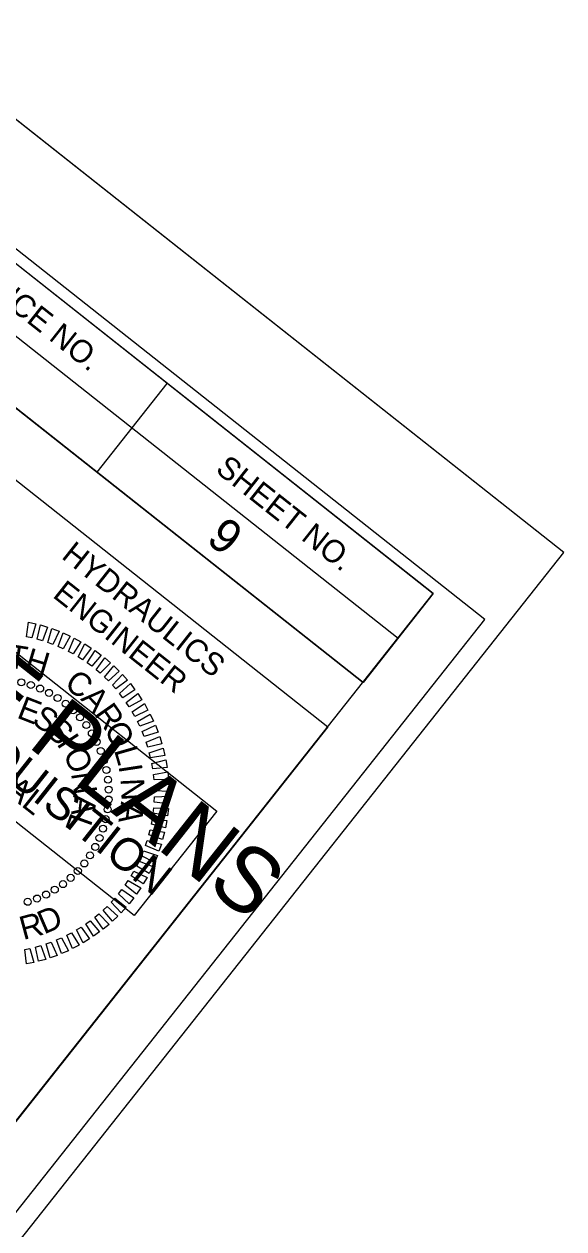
# Model space of a CAD drawing. Extents: x 556999 to 559002, y 505273 to 507273.
# Drawn here: x 558883.2 to 559002.4, y 506079.3 to 506345.6 of the extents above; entities that cross this region are included whole.
import ezdxf

# ---------------------------------------------------------------- set-up
doc = ezdxf.new("R2010")
doc.units = 0
for name, color, linetype in [('Old_Level_21', 7, 'Continuous'), ('Sheet Border Standard 30in CELL', 7, 'Continuous'), ('Sheet Cutting Line CELL', 7, 'Continuous'), ('Sheet Data Field CELL', 7, 'Continuous'), ('Sheet Plot Border Inside CELL', 7, 'Continuous'), ('Sheet Plot Border Outside CELL', 7, 'Continuous'), ('Sheet Sticker Incomplete CELL', 7, 'Continuous')]:
    doc.layers.add(name, color=color, linetype=linetype)

msp = doc.modelspace()

# ---------------------------------------------------------------- linework, layer by layer
at = {"layer": 'Old_Level_21'}
for points in [[(558883.69, 506210.18), (558884.14, 506213.39), (558885.77, 506213), (558884.85, 506209.94)], [(558886.08, 506209.62), (558886.75, 506212.78), (558888.35, 506212.28), (558887.22, 506209.29)], [(558888.43, 506208.88), (558889.32, 506211.99), (558890.88, 506211.38), (558889.54, 506208.48)], [(558890.72, 506207.99), (558891.82, 506211.02), (558893.33, 506210.31), (558891.8, 506207.51)], [(558892.94, 506206.93), (558894.25, 506209.89), (558895.71, 506209.07), (558893.98, 506206.38)], [(558895.08, 506205.73), (558896.6, 506208.58), (558898, 506207.66), (558896.08, 506205.1)], [(558897.13, 506204.38), (558898.85, 506207.12), (558900.18, 506206.1), (558898.09, 506203.68)], [(558899.09, 506202.88), (558900.99, 506205.5), (558902.24, 506204.39), (558899.99, 506202.12)], [(558900.93, 506201.26), (558903.01, 506203.74), (558904.19, 506202.55), (558901.78, 506200.44)], [(558902.66, 506199.51), (558904.9, 506201.84), (558905.99, 506200.57), (558903.45, 506198.63)], [(558904.26, 506197.64), (558906.66, 506199.81), (558907.66, 506198.47), (558904.99, 506196.71)], [(558905.73, 506195.67), (558908.27, 506197.66), (558909.18, 506196.25), (558906.39, 506194.69)], [(558907.05, 506193.6), (558909.73, 506195.41), (558910.53, 506193.94), (558907.64, 506192.58)], [(558908.23, 506191.44), (558911.03, 506193.06), (558911.73, 506191.54), (558908.75, 506190.38)], [(558909.25, 506189.21), (558912.16, 506190.63), (558912.75, 506189.06), (558909.7, 506188.11)], [(558910.12, 506186.91), (558913.12, 506188.12), (558913.6, 506186.52), (558910.49, 506185.78)], [(558910.82, 506184.55), (558913.9, 506185.55), (558914.27, 506183.92), (558911.11, 506183.41)], [(558911.36, 506182.15), (558914.5, 506182.94), (558914.75, 506181.28), (558911.57, 506180.99)], [(558911.73, 506179.72), (558914.92, 506180.29), (558915.05, 506178.62), (558911.86, 506178.55)], [(558911.93, 506177.27), (558915.15, 506177.61), (558915.16, 506175.94), (558911.97, 506176.09)], [(558911.96, 506174.82), (558915.19, 506174.93), (558915.09, 506173.26), (558911.92, 506173.63)], [(558911.81, 506172.36), (558915.04, 506172.25), (558914.83, 506170.59), (558911.69, 506171.19)], [(558911.5, 506169.92), (558914.71, 506169.59), (558914.38, 506167.95), (558911.29, 506168.76)], [(558911.01, 506167.51), (558914.2, 506166.95), (558913.75, 506165.34), (558910.73, 506166.37)], [(558910.36, 506165.14), (558913.5, 506164.36), (558912.94, 506162.78), (558910, 506164.02)], [(558909.55, 506162.83), (558912.62, 506161.83), (558911.96, 506160.29), (558909.1, 506161.73)], [(558908.57, 506160.57), (558911.57, 506159.36), (558910.8, 506157.87), (558908.05, 506159.5)], [(558906.16, 506156.29), (558908.96, 506154.67), (558907.99, 506153.31), (558905.5, 506155.3)], [(558907.44, 506158.39), (558910.35, 506156.97), (558909.48, 506155.54), (558906.85, 506157.36)], [(558904.74, 506154.28), (558907.42, 506152.47), (558906.36, 506151.18), (558904.01, 506153.35)], [(558901.49, 506150.59), (558903.9, 506148.43), (558902.66, 506147.3), (558900.64, 506149.77)], [(558903.18, 506152.38), (558905.73, 506150.39), (558904.58, 506149.17), (558902.39, 506151.5)], [(558899.68, 506148.93), (558901.93, 506146.6), (558900.62, 506145.56), (558898.78, 506148.17)], [(558895.74, 506146), (558897.64, 506143.38), (558896.2, 506142.53), (558894.74, 506145.37)], [(558897.76, 506147.39), (558899.84, 506144.92), (558898.47, 506143.97), (558896.81, 506146.7)], [(558889.16, 506142.7), (558890.48, 506139.74), (558888.89, 506139.21), (558888.05, 506142.29)], [(558891.43, 506143.64), (558892.95, 506140.79), (558891.4, 506140.14), (558890.35, 506143.16)], [(558893.63, 506144.74), (558895.34, 506142), (558893.84, 506141.25), (558892.58, 506144.19)], [(558884.45, 506141.29), (558885.34, 506138.18), (558883.7, 506137.87), (558883.29, 506141.04)], [(558886.83, 506141.91), (558887.94, 506138.87), (558886.32, 506138.45), (558885.69, 506141.58)]]:
    msp.add_lwpolyline(points, close=True, dxfattribs=at)
for centre in [(558882.54, 506200.1), (558884.65, 506199.51), (558886.7, 506198.73), (558888.67, 506197.77), (558890.55, 506196.65), (558892.33, 506195.37), (558893.99, 506193.93), (558895.52, 506192.36), (558896.9, 506190.66), (558898.13, 506188.85), (558899.2, 506186.93), (558900.1, 506184.94), (558900.82, 506182.86), (558901.36, 506180.74), (558901.7, 506178.58), (558901.86, 506176.39), (558901.83, 506174.2), (558901.61, 506172.02), (558901.2, 506169.86), (558899.82, 506165.71), (558900.6, 506167.76), (558898.87, 506163.73), (558897.74, 506161.85), (558895.03, 506158.42), (558896.46, 506160.07), (558891.76, 506155.5), (558893.45, 506156.89), (558888.03, 506153.2), (558889.94, 506154.27), (558883.96, 506151.59), (558886.03, 506152.31)]:
    msp.add_circle(centre, 0.777, dxfattribs=at)
at = {"layer": 'Sheet Border Standard 30in CELL'}
for p, q in [((558808.87, 506333.95), (558965.79, 506209.87)), ((558801.12, 506324.14), (558958.04, 506200.06)), ((558801.12, 506324.14), (558958.04, 506200.06)), ((558914.71, 506266.19), (558899.21, 506246.58))]:
    msp.add_line(p, q, dxfattribs=at)
for points in [[(558973.57, 506219.71), (557796.95, 507150.06), (557145.7, 506326.43), (558322.33, 505396.07)], [(558816.65, 506343.79), (558973.57, 506219.71), (558958.04, 506200.06), (558801.12, 506324.14)], [(558871.84, 506252.28), (558950.28, 506190.26), (558880.51, 506102.01), (558802.07, 506164.03)]]:
    msp.add_lwpolyline(points, close=True, dxfattribs=at)
at = {"layer": 'Sheet Cutting Line CELL'}
msp.add_line((559002.42, 506228.78), (557681.46, 507273.25), dxfattribs=at)
at = {"layer": 'Sheet Plot Border Inside CELL'}
msp.add_lwpolyline([(558984.96, 506213.96), (557677.73, 507247.58), (557023.32, 506419.94), (558330.55, 505386.32)], close=True, dxfattribs=at)
at = {"layer": 'Sheet Plot Border Outside CELL'}
msp.add_lwpolyline([(559002.42, 506228.78), (557681.46, 507273.25), (556999.2, 506410.4), (558320.16, 505365.92)], close=True, dxfattribs=at)
at = {"layer": 'Sheet Sticker Incomplete CELL'}
msp.add_lwpolyline([(558763.37, 506262.57), (558781.59, 506285.61), (558925.73, 506171.64), (558907.51, 506148.6)], close=True, dxfattribs=at)

# ---------------------------------------------------------------- texts
at = {"layer": 'Old_Level_21'}
for s, height, rotation, p in [('T', 5.18, 351.0641, (558879.28, 506203.44)), ('H', 5.18, 343.2748, (558883.03, 506202.85)), ('C', 5.18, 323.6356, (558891.8, 506199.15)), ('A', 5.18, 314.1306, (558895.47, 506196.35)), ('E', 5.18, 338.6598, (558881.33, 506192.36)), ('S', 5.18, 326.8975, (558884.64, 506191.08)), ('R', 5.18, 305.0831, (558898.49, 506193.14)), ('S', 5.18, 314.9386, (558887.66, 506189.11)), ('O', 5.18, 296.8744, (558900.77, 506189.86)), ('I', 5.18, 302.9796, (558890.21, 506186.55)), ('O', 5.18, 294.2242, (558891.71, 506184.38)), ('L', 5.18, 286.1493, (558902.99, 506185.14)), ('SEAL', 5.181, 321.6738, (558871.48, 506181.47)), ('N', 5.18, 278.4154, (558893.52, 506179.97)), ('I', 5.18, 278.6841, (558904, 506181.65)), ('N', 5.18, 272.7442, (558904.48, 506178.8)), ('A', 5.18, 263.3653, (558894.07, 506175.47)), ('A', 5.18, 262.5337, (558904.59, 506173.84)), ('L', 5.18, 250.0294, (558893.56, 506171.48)), ('D', 5.18, 23.3743, (558887.55, 506144.34)), ('R', 5.18, 15.1656, (558882.97, 506143.12))]:
    msp.add_text(s, height=height, rotation=rotation, dxfattribs=at).set_placement(p)
at = {"layer": 'Sheet Border Standard 30in CELL'}
for s, height, p in [('PROJECT REFERENCE NO.', 5.0001, (558828.67, 506323.2)), ('SHEET NO.', 5, (558925.21, 506246.74)), ('HYDRAULICS', 5, (558891.2, 506227.67)), ('ENGINEER', 5, (558889.25, 506219.07))]:
    msp.add_text(s, height=height, rotation=321.6667, dxfattribs=at).set_placement(p)
at = {"layer": 'Sheet Data Field CELL'}
msp.add_text('9  ', height=7.5, rotation=321.6667, dxfattribs=at).set_placement((558923.13, 506231.23))
at = {"layer": 'Sheet Sticker Incomplete CELL'}
for s, height, p in [('INCOMPLETE PLANS', 14.4, (558781.24, 506267.11)), ('DO NOT USE FOR R/W ACQUISITION', 7.2, (558779.04, 506257.77))]:
    msp.add_text(s, height=height, rotation=321.6667, dxfattribs=at).set_placement(p)

doc.saveas('drawing.dxf')
